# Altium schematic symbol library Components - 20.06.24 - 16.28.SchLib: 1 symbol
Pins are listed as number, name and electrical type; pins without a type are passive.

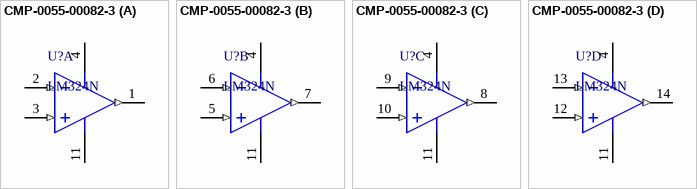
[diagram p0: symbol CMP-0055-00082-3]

## CMP-0055-00082-3
designator U?, comment LM324N
Low Power Quad Operational Amplifier, 14-pin MDIP; Manufacturer: Texas Instruments; CompType: Amplifiers; PowerWise: N; PackageTopMarking: NSUZXYYTTE#*LM324N
footprint N0014A (DIP, 14-Leads, Body 19.7x6.6mm, Pitch 2.54mm)
pins on every part: 4 V+ (power), 11 GND (power)
part A pins: 1 OUT1 (out), 2 IN1- (in), 3 IN1+ (in)
part B pins: 5 IN2+ (in), 6 IN2- (in), 7 OUT2 (out)
part C pins: 8 OUT3 (out), 9 IN3- (in), 10 IN3+ (in)
part D pins: 12 IN4+ (in), 13 IN4- (in), 14 OUT4 (out)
